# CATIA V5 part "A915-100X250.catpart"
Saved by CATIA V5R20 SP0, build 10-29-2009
Part number: A915-100X250
Source: Unknown
Property "A": "0.000"
Property "ARTICLENO": "A915-100X250"
Property "BOMINFO": "A915-100X250"
Property "CODE": "A915-100X250"
Property "CREATOR": "CADENAS GmbH"
Property "D": "13.500"
Property "D1": "20.000"
Property "FORM": "B"
Property "L": "250.000"
Property "L1": "40.000"
Property "L2": "170.000"
Property "LINA": "A915-100X250"
Property "NB": "A915-100X250"
Property "NBSYN": "$CODE."
Property "NN": "A915"
Property "NT": "VDI 3357 Wear Plates, steel"
Property "SCREW": "M12x25"
Property "SUPPLIER": "CF"
Property "T": "13.000"
Property "W": "100.000"
Bounding box of the stored display mesh (mm): x 0 to 20, y 0 to 250, z -50 to 50
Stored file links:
  C:\Users\borellobunino\Desktop\3D X SITO CF\A915\GSB_OILLESS_G22501100250\CATIAV5\A915-100X250.catpart
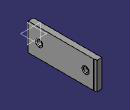
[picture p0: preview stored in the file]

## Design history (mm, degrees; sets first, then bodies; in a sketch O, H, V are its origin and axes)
Body1 "Geometry.1" (main body)
  Solid1 "A915-100X250.catpart": solid without history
